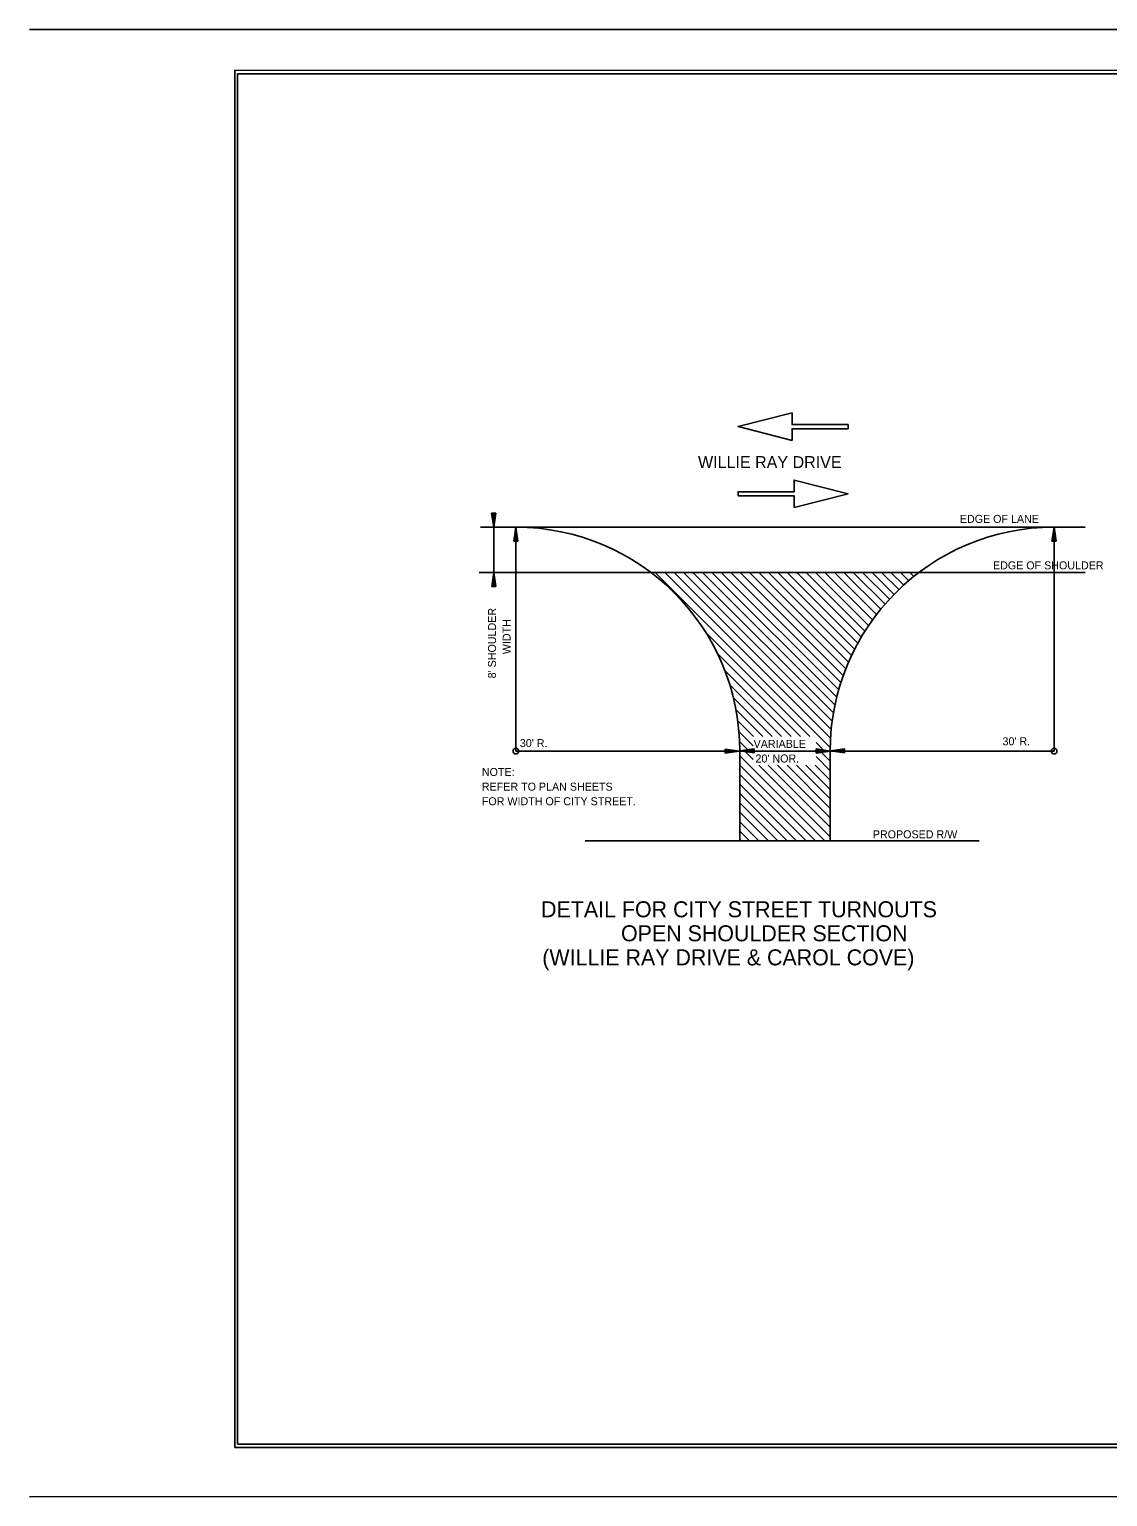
# Model space of a CAD drawing. Extents: x 714919 to 718439, y 1619644 to 1621844.
# Drawn here: x 714919 to 716536, y 1619644 to 1621844 of the extents above; entities that cross this region are included whole.
import ezdxf

# ---------------------------------------------------------------- set-up
doc = ezdxf.new("R2010")
doc.units = 0
for name, color, linetype in [('Default', 7, 'Continuous'), ('Drainage', 7, 'Continuous'), ('R_Border', 7, 'Continuous'), ('R_No Plot', 7, 'Continuous')]:
    doc.layers.add(name, color=color, linetype=linetype)

msp = doc.modelspace()

# ---------------------------------------------------------------- linework, layer by layer
at = {"layer": 'Default'}
for p, q in [((715612.4, 1621118.5), (715615.6, 1621097.3)), ((715618.8, 1621118.5), (715612.4, 1621118.5)), ((715612.9, 1621118.5), (715615.6, 1621100.8)), ((715613.5, 1621118.5), (715615.6, 1621104.5)), ((715614.1, 1621118.5), (715615.6, 1621108)), ((715614.6, 1621118.5), (715615.6, 1621111.6)), ((715615.1, 1621118.5), (715615.6, 1621115.1)), ((715618.8, 1621118.5), (715615.6, 1621097.3)), ((715616.6, 1621118.5), (715615.6, 1621111.6)), ((715617.8, 1621118.5), (715615.6, 1621104.5)), ((715618.3, 1621118.5), (715615.6, 1621100.8)), ((715617.2, 1621118.5), (715615.6, 1621108)), ((715616.1, 1621118.5), (715615.6, 1621115.1)), ((715595.5, 1621097.3), (716502.5, 1621097.3)), ((715615.6, 1621029.5), (715615.6, 1621097.3)), ((715645.5, 1621076.1), (715648.8, 1621097.3)), ((715646.1, 1621076.1), (715648.8, 1621093.8)), ((716455.9, 1621097.3), (715648.7, 1621097.3)), ((715651.9, 1621076.1), (715648.8, 1621097.3)), ((715648.8, 1621097.3), (715648.8, 1620761.5)), ((715651.4, 1621076.1), (715648.8, 1621093.8)), ((715975.4, 1621096.6), (715975.7, 1621097.5)), ((715975.7, 1621097.2), (715975.4, 1621096.6)), ((715975.4, 1621096.6), (715975.7, 1621096.9)), ((716452.7, 1621076.1), (716455.9, 1621097.3)), ((716459.1, 1621076.1), (716455.9, 1621097.3)), ((716455.9, 1620761.5), (716455.9, 1621097.3)), ((715645.5, 1621076.1), (715651.9, 1621076.1)), ((715646.6, 1621076.1), (715648.8, 1621090.1)), ((715647.1, 1621076.1), (715648.8, 1621086.6)), ((715647.7, 1621076.1), (715648.8, 1621083)), ((715648.2, 1621076.1), (715648.8, 1621079.5)), ((715650.8, 1621076.1), (715648.8, 1621090.1)), ((715650.3, 1621076.1), (715648.8, 1621086.6)), ((715649.8, 1621076.1), (715648.8, 1621083)), ((715649.2, 1621076.1), (715648.8, 1621079.5)), ((716452.7, 1621076.1), (716459.1, 1621076.1)), ((716453.2, 1621076.1), (716455.9, 1621093.7)), ((716453.8, 1621076.1), (716455.9, 1621090.1)), ((716454.3, 1621076.1), (716455.9, 1621086.6)), ((716454.8, 1621076.1), (716455.9, 1621082.9)), ((716455.3, 1621076.1), (716455.9, 1621079.4)), ((716458.5, 1621076.1), (716455.9, 1621093.7)), ((716458, 1621076.1), (716455.9, 1621090.1)), ((716457.4, 1621076.1), (716455.9, 1621086.6)), ((716457, 1621076.1), (716455.9, 1621082.9)), ((716456.4, 1621076.1), (716455.9, 1621079.4)), ((715593.6, 1621029.5), (716502.5, 1621029.5)), ((715612.5, 1621008.3), (715615.6, 1621029.5)), ((715618.8, 1621008.3), (715615.6, 1621029.5)), ((716120.1, 1620767.1), (715857.7, 1621029.5)), ((716120.6, 1620780.8), (715871.9, 1621029.5)), ((716121.6, 1620793.9), (715886, 1621029.5)), ((716123.1, 1620806.6), (715900.1, 1621029.5)), ((716125, 1620818.8), (715914.3, 1621029.5)), ((716127.3, 1620830.7), (715928.4, 1621029.5)), ((716129.9, 1620842.2), (715942.6, 1621029.5)), ((716132.9, 1620853.4), (715956.7, 1621029.5)), ((716136.2, 1620864.2), (715970.9, 1621029.5)), ((716139.8, 1620874.8), (715985, 1621029.5)), ((716143.6, 1620885.1), (715999.1, 1621029.5)), ((716147.8, 1620895.1), (716013.3, 1621029.5)), ((716152.2, 1620904.8), (716027.4, 1621029.5)), ((716156.8, 1620914.3), (716041.6, 1621029.5)), ((716161.7, 1620923.5), (716055.7, 1621029.5)), ((716166.9, 1620932.5), (716069.9, 1621029.5)), ((716172.2, 1620941.3), (716084, 1621029.5)), ((716177.8, 1620949.8), (716098.1, 1621029.5)), ((716183.7, 1620958.2), (716112.3, 1621029.5)), ((716189.7, 1620966.3), (716126.4, 1621029.5)), ((716196, 1620974.1), (716140.6, 1621029.5)), ((716202.4, 1620981.8), (716154.7, 1621029.5)), ((716209.1, 1620989.3), (716168.8, 1621029.5)), ((716216, 1620996.5), (716183, 1621029.5)), ((716223.1, 1621003.6), (716197.1, 1621029.5)), ((716230.4, 1621010.4), (716211.3, 1621029.5)), ((716238, 1621017), (716225.4, 1621029.5)), ((716245.7, 1621023.4), (716239.6, 1621029.5)), ((715612.5, 1621008.3), (715618.8, 1621008.3)), ((715612.9, 1621008.3), (715615.6, 1621025.9)), ((715613.5, 1621008.3), (715615.6, 1621022.3)), ((715614, 1621008.3), (715615.6, 1621018.8)), ((715614.6, 1621008.3), (715615.6, 1621015.2)), ((715615.1, 1621008.3), (715615.6, 1621011.6)), ((715618.3, 1621008.3), (715615.6, 1621025.9)), ((715617.8, 1621008.3), (715615.6, 1621022.3)), ((715617.2, 1621008.3), (715615.6, 1621018.8)), ((715616.6, 1621008.3), (715615.6, 1621015.2)), ((715616.1, 1621008.3), (715615.6, 1621011.6)), ((716089.7, 1620783.4), (715933.2, 1620940)), ((716075.6, 1620783.4), (715950.8, 1620908.2)), ((716061.5, 1620783.4), (715961.7, 1620883.1)), ((716047.3, 1620783.4), (715969.3, 1620861.4)), ((716033.2, 1620783.4), (715974.8, 1620841.8)), ((716019, 1620783.4), (715978.7, 1620823.7)), ((716004.9, 1620783.4), (715981.4, 1620806.8)), ((716004.5, 1620769.6), (715983.2, 1620790.9)), ((715962.5, 1620764.5), (715983.7, 1620761.4)), ((715962.5, 1620764.5), (715962.5, 1620758.2)), ((715962.5, 1620764), (715980.1, 1620761.4)), ((715996.4, 1620763.6), (715984.2, 1620775.8)), ((716006, 1620765), (715984.8, 1620761.8)), ((716006, 1620764.5), (715988.4, 1620761.8)), ((716006, 1620764), (715992, 1620761.8)), ((716006, 1620758.7), (716006, 1620765)), ((716110.1, 1620763), (716098.9, 1620774.2)), ((716098.9, 1620764.7), (716120.1, 1620761.5)), ((716098.9, 1620764.7), (716098.9, 1620758.3)), ((716098.9, 1620764.2), (716116.5, 1620761.5)), ((716141.6, 1620765), (716120.4, 1620761.8)), ((716141.6, 1620764.5), (716123.9, 1620761.8)), ((716141.6, 1620764), (716127.6, 1620761.8)), ((716141.6, 1620758.7), (716141.6, 1620765)), ((715648.7, 1620761.5), (715984.5, 1620761.5)), ((715962.5, 1620763.5), (715976.5, 1620761.4)), ((715962.5, 1620762.9), (715972.9, 1620761.4)), ((715962.5, 1620762.4), (715969.3, 1620761.4)), ((715962.5, 1620761.8), (715965.8, 1620761.4)), ((715962.5, 1620758.2), (715983.7, 1620761.4)), ((715962.5, 1620760.3), (715969.3, 1620761.4)), ((715962.5, 1620759.2), (715976.5, 1620761.4)), ((715962.5, 1620758.7), (715980.1, 1620761.4)), ((715962.5, 1620759.8), (715972.9, 1620761.4)), ((715962.5, 1620760.8), (715965.8, 1620761.4)), ((715984.5, 1620761.5), (715984.5, 1620626.9)), ((715984.5, 1620761.5), (716120.1, 1620761.5)), ((715984.5, 1620761.5), (716120.1, 1620761.5)), ((716112.2, 1620626.9), (715984.5, 1620754.6)), ((716006, 1620758.7), (715984.8, 1620761.8)), ((716006, 1620759.2), (715988.4, 1620761.8)), ((716006, 1620759.7), (715992, 1620761.8)), ((716004.5, 1620748.7), (715992.6, 1620760.7)), ((716006, 1620763.4), (715995.5, 1620761.8)), ((716006, 1620760.3), (715995.5, 1620761.8)), ((716006, 1620762.9), (715999.1, 1620761.8)), ((716006, 1620760.8), (715999.1, 1620761.8)), ((716006, 1620762.3), (716002.6, 1620761.8)), ((716006, 1620761.3), (716002.6, 1620761.8)), ((716098.9, 1620763.6), (716112.9, 1620761.5)), ((716098.9, 1620763), (716109.4, 1620761.5)), ((716098.9, 1620762.5), (716105.8, 1620761.5)), ((716098.9, 1620762), (716102.2, 1620761.5)), ((716098.9, 1620758.3), (716120.1, 1620761.5)), ((716098.9, 1620760.4), (716105.8, 1620761.5)), ((716098.9, 1620759.4), (716112.9, 1620761.5)), ((716098.9, 1620758.8), (716116.5, 1620761.5)), ((716098.9, 1620759.9), (716109.4, 1620761.5)), ((716098.9, 1620761), (716102.2, 1620761.5)), ((716120.1, 1620732.1), (716098.9, 1620753.3)), ((716120.1, 1620746.3), (716106.9, 1620759.5)), ((716120.1, 1620760.4), (716119.1, 1620761.4)), ((716120.1, 1620626.9), (716120.1, 1620761.5)), ((716120.1, 1620761.5), (716455.9, 1620761.5)), ((716141.6, 1620758.7), (716120.4, 1620761.8)), ((716141.6, 1620759.2), (716123.9, 1620761.8)), ((716141.6, 1620759.7), (716127.6, 1620761.8)), ((716141.6, 1620763.4), (716131.1, 1620761.8)), ((716141.6, 1620760.3), (716131.1, 1620761.8)), ((716141.6, 1620762.9), (716134.7, 1620761.8)), ((716141.6, 1620760.8), (716134.7, 1620761.8)), ((716141.6, 1620762.3), (716138.2, 1620761.8)), ((716141.6, 1620761.3), (716138.2, 1620761.8)), ((716098.1, 1620626.9), (715984.5, 1620740.4)), ((716083.9, 1620626.9), (715984.5, 1620726.3)), ((716120.1, 1620633.1), (716013, 1620740.3)), ((716120.1, 1620647.3), (716027.1, 1620740.3)), ((716120.1, 1620661.4), (716041.3, 1620740.3)), ((716120.1, 1620675.5), (716055.4, 1620740.3)), ((716120.1, 1620689.7), (716069.5, 1620740.3)), ((716120.1, 1620703.8), (716083.7, 1620740.3)), ((716120.1, 1620718), (716097.8, 1620740.3)), ((716069.8, 1620626.9), (715984.5, 1620712.1)), ((716055.6, 1620626.9), (715984.5, 1620698)), ((716041.5, 1620626.9), (715984.5, 1620683.8)), ((716027.4, 1620626.9), (715984.5, 1620669.7)), ((716013.2, 1620626.9), (715984.5, 1620655.6)), ((715999.1, 1620626.9), (715984.5, 1620641.4)), ((715752.5, 1620626.9), (716343.7, 1620626.9)), ((715984.9, 1620626.9), (715984.5, 1620627.3))]:
    msp.add_line(p, q, dxfattribs=at)
for centre, radius in [((715648.7, 1620761.5), 4.23), ((716455.9, 1620761.5), 4.24)]:
    msp.add_circle(centre, radius, dxfattribs=at)
for centre, start, end in [((715648.7, 1620761.5), 0, 90), ((715648.7, 1620761.5), 0, 90), ((716455.9, 1620761.5), 90, 180), ((716455.9, 1620761.5), 90, 180)]:
    msp.add_arc(centre, 335.8, start, end, dxfattribs=at)
at = {"layer": 'Drainage'}
for points in [[(716146.9, 1621251), (716062.9, 1621251), (716062.9, 1621268.5), (715982.1, 1621248), (716062.9, 1621227.4), (716062.9, 1621244.9), (716146.9, 1621244.9)], [(715982.1, 1621144.4), (716066.1, 1621144.4), (716066.1, 1621126.9), (716146.9, 1621147.4), (716066.1, 1621167.9), (716066.1, 1621150.4), (715982.1, 1621150.4)]]:
    msp.add_lwpolyline(points, close=True, dxfattribs=at)
at = {"layer": 'R_Border'}
for p, q in [((718439, 1621843.8), (714919, 1621843.5)), ((715231.2, 1619722.5), (715231.3, 1621777.1)), ((715231.3, 1621777.1), (718393.1, 1621777.1)), ((718393.2, 1619722.5), (715231.2, 1619722.5)), ((714919.1, 1619643.5), (718439.3, 1619643.8))]:
    msp.add_line(p, q, dxfattribs=at)
at = {"layer": 'R_No Plot'}
msp.add_lwpolyline([(715227.2, 1619717.3), (718397.1, 1619717.4), (718397.2, 1621782.5), (715227.1, 1621782.3)], close=True, dxfattribs=at)

# ---------------------------------------------------------------- texts
at = {"layer": 'Default'}
for s, height, p in [('WILLIE RAY DRIVE', 18, (715921.9, 1621185.8)), ('EDGE OF LANE', 12, (716314.6, 1621103.7)), ('EDGE OF SHOULDER', 12, (716364.3, 1621034)), ("30' R.", 12, (715654.7, 1620767.5)), ('VARIABLE', 12, (716005.3, 1620766.3)), ("30' R.", 12, (716378.6, 1620770.2)), ("20' NOR.", 12, (716008.1, 1620744.4)), ('NOTE:', 12, (715597.7, 1620724.2)), ('REFER TO PLAN SHEETS', 12, (715597.7, 1620702.2)), ('FOR WIDTH OF CITY STREET.', 12, (715597.7, 1620680.3)), ('PROPOSED R/W', 12, (716184.1, 1620630.7)), ('DETAIL FOR CITY STREET TURNOUTS', 24, (715686.5, 1620512.3)), ('OPEN SHOULDER SECTION', 24, (715806.4, 1620476.3)), ('(WILLIE RAY DRIVE & CAROL COVE)', 24, (715688.3, 1620440.2))]:
    msp.add_text(s, height=height, dxfattribs=at).set_placement(p)
for s, p in [("8' SHOULDER", (715618.9, 1620870.6)), ('WIDTH', (715640.8, 1620906.8))]:
    msp.add_text(s, height=12, rotation=90, dxfattribs=at).set_placement(p)

doc.saveas('drawing.dxf')
